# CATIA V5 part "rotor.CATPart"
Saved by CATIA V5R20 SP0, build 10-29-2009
Part number: rotor
Bounding box of the stored display mesh (mm): x -27.78 to 27.78, y -30 to 40, z -10 to 10
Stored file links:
  D:\Documents and Settings\mosavian\My Documents\DMU Project3\New Folder\rotor.CATPart
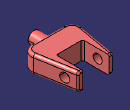
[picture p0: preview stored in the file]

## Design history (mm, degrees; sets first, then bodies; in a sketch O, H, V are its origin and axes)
Body1 (main body)
  Sketch1 on xy-plane, origin (0, 0, 0), H (1, 0, 0), V (0, 1, 0)
    line L1 (-22.5, -15) -> (-28.619, -8.881)
    line L2 (-28.619, -8.881) -> (-20, 40)
    line L3 (-20, 40) -> (-15, 40)
    line L4 (-15, 40) -> (-15, 10)
    line L5 (-15, 10) -> (15, 10)
    line L6 (15, 10) -> (15, 40)
    point P7 (15, 40)
    line L7 (15, 40) -> (20, 40)
    line L8 (20, 40) -> (28.619, -8.881)
    line L9 (28.619, -8.881) -> (22.5, -15)
    line L10 (-22.5, -15) -> (22.5, -15)
    length L5 = 30
    length L3 = 5
    angle L2 L8 = 20
    length L6 = 30
    angle L9 H = 45
    length L10 = 45
    distance L7 H = 40
    distance L10 H = 15
    horizontal: L3 H, L5 H, L7 H, L10 H
    vertical: L4 V, L6 V
    coincidence: P7 L3
    symmetry: L8 L2 V, L9 L1 V, L4 L6 V
  Pad1: profile Sketch1, direction (0, 0, 1), length 10, mirrored extent
  Fillet1: radius 10, on edge [face of Pad1 from Sketch1.L8 | face of Pad1 from Sketch1.L9]; edge [face of Pad1 from Sketch1.L1 | face of Pad1 from Sketch1.L2]; edge [face of Pad1 from Sketch1.L9 | face of Pad1 from Sketch1.L10]; edge [face of Pad1 from Sketch1.L10 | face of Pad1 from Sketch1.L1]
  Fillet2: radius 3, on edge [face of Pad1 from Sketch1.L8 | end face of Pad1]; edge [start face of Pad1 | face of Pad1 from Sketch1.L8]
  Fillet3: radius 2, on edge [face of Pad1 from Sketch1.L7 | face of Pad1 from Sketch1.L8]; edge [face of Pad1 from Sketch1.L3 | face of Fillet2]
  Fillet4: radius 2, on edge [face of Pad1 from Sketch1.L4 | face of Pad1 from Sketch1.L5]; edge [face of Pad1 from Sketch1.L5 | face of Pad1 from Sketch1.L6]
  Sketch2 on face of Pad1 from Sketch1.L4, origin (-15, 0, 0), H (0, 1, 0), V (0, 0, 1)
    circle A1 centre (27, 0) radius 5
    point P1 (27, 0)
    reference projected line E1 (40, -10) -> (40, 10) from edge [face of Pad1 from Sketch1.L3 | face of Pad1 from Sketch1.L4]
    radius A1 = 5
    distance P1 E1 = 13
    coincidence: P1 H
  Pocket1: profile Sketch2, direction (-1, 0, 0), through (limit type 6), opposite side through (limit type 3)
  Sketch3 on face of Pad1 from Sketch1.L10, origin (0, -15, 0), H (1, 0, 0), V (0, 0, 1)
    circle A1 centre (0, 0) radius 6.5
    radius A1 = 6.5
  Pad2: profile Sketch3, direction (0, -1, 0), length 15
